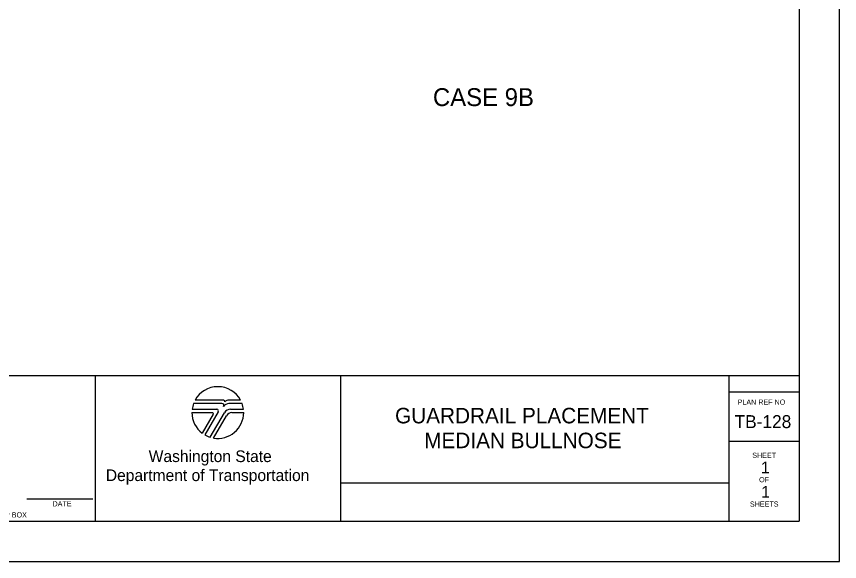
# Model space of a CAD drawing. Extents: x 1312564.5 to 1312581.5, y 1207298.4 to 1207309.4.
# Drawn here: x 1312575.12 to 1312581.48, y 1207298.42 to 1207302.64 of the extents above; entities that cross this region are included whole.
import ezdxf

# ---------------------------------------------------------------- set-up
doc = ezdxf.new("R2010")
doc.units = 0
for name, color, linetype in [('Level 1', 7, 'Continuous'), ('Level 20', 7, 'Continuous'), ('SH_GI_PlotLimits', 7, 'Continuous'), ('SH_GI_SheetBorder', 7, 'Continuous'), ('SH_GI_SheetTextInCells', 7, 'Continuous'), ('SH_GI_TitleBlockText', 7, 'Continuous'), ('SH_GI_WSDOTLogo', 7, 'Continuous')]:
    doc.layers.add(name, color=color, linetype=linetype)

msp = doc.modelspace()

# ---------------------------------------------------------------- linework, layer by layer
at = {"layer": 'SH_GI_PlotLimits'}
msp.add_lwpolyline([(1312564.478, 1207298.4209), (1312581.478, 1207298.4209), (1312581.478, 1207309.4209), (1312564.478, 1207309.4209)], close=True, dxfattribs=at)
at = {"layer": 'SH_GI_SheetBorder'}
for p, q in [((1312581.1655, 1207309.1084), (1312581.1655, 1207298.7334)), ((1312565.4155, 1207299.8593), (1312581.1655, 1207299.8593)), ((1312575.7244, 1207299.8593), (1312575.7244, 1207298.7334)), ((1312577.621, 1207299.8593), (1312577.621, 1207298.7334)), ((1312580.6233, 1207299.8593), (1312580.6233, 1207298.7334)), ((1312580.6233, 1207299.7342), (1312581.1655, 1207299.7342)), ((1312580.6233, 1207299.351), (1312581.1655, 1207299.351)), ((1312577.621, 1207299.0289), (1312580.6233, 1207299.0289)), ((1312575.1952, 1207298.9067), (1312575.7069, 1207298.9067)), ((1312565.4155, 1207298.7334), (1312581.1655, 1207298.7334))]:
    msp.add_line(p, q, dxfattribs=at)
at = {"layer": 'SH_GI_WSDOTLogo'}
for p, q in [((1312576.7185, 1207299.6688), (1312576.497, 1207299.6688)), ((1312576.8485, 1207299.6688), (1312576.7506, 1207299.6688)), ((1312576.4745, 1207299.5995), (1312576.6651, 1207299.5995)), ((1312576.7049, 1207299.6428), (1312576.4852, 1207299.6428)), ((1312576.7585, 1207299.6428), (1312576.7584, 1207299.6428)), ((1312576.8603, 1207299.6428), (1312576.7585, 1207299.6428)), ((1312576.7713, 1207299.5995), (1312576.871, 1207299.5995)), ((1312576.4727, 1207299.5734), (1312576.6303, 1207299.5734)), ((1312576.6374, 1207299.5611), (1312576.5519, 1207299.4141)), ((1312576.6765, 1207299.5798), (1312576.5722, 1207299.4006)), ((1312576.6144, 1207299.3822), (1312576.7244, 1207299.5724)), ((1312576.6399, 1207299.3762), (1312576.7397, 1207299.549)), ((1312576.7809, 1207299.5728), (1312576.8727, 1207299.5728))]:
    msp.add_line(p, q, dxfattribs=at)
for centre, radius, start, end in [((1312576.6727, 1207299.5734), 0.2, 28.47865, 151.53204), ((1312576.7184, 1207299.6597), 0.00903, 329.87418, 90.00328), ((1312576.7506, 1207299.6401), 0.0287, 90.00721, 148.16763), ((1312576.6727, 1207299.5734), 0.2, 159.69598, 172.50569), ((1312576.6651, 1207299.5864), 0.0131, 329.76834, 90), ((1312576.7049, 1207299.628), 0.0148, 327.8418, 89.99855), ((1312576.7584, 1207299.5944), 0.0484, 89.99529, 147.82376), ((1312576.7713, 1207299.5454), 0.0542, 90, 149.99738), ((1312576.6727, 1207299.5734), 0.2, 7.49431, 20.29406), ((1312576.6727, 1207299.5734), 0.2, 179.99864, 232.84327), ((1312576.6303, 1207299.5652), 0.0082, 329.74356, 90), ((1312576.6727, 1207299.5734), 0.2, 260.54554, 359.80857), ((1312576.7809, 1207299.5252), 0.0476, 90, 150.05432), ((1312576.6727, 1207299.5734), 0.2, 239.79292, 253.0448)]:
    msp.add_arc(centre, radius, start, end, dxfattribs=at)

# ---------------------------------------------------------------- texts
at = {"layer": 'Level 1'}
msp.add_text('CASE 9B', height=0.13824, dxfattribs=at).set_placement((1312578.3352, 1207301.944))
at = {"layer": 'Level 20'}
for s, p in [('GUARDRAIL PLACEMENT', (1312578.0426, 1207299.4898)), ('MEDIAN BULLNOSE', (1312578.2679, 1207299.2978))]:
    msp.add_text(s, height=0.12, dxfattribs=at).set_placement(p)
at = {"layer": 'SH_GI_SheetBorder'}
msp.add_text('PLAN REF NO', height=0.040032, dxfattribs=at).set_placement((1312580.6902, 1207299.6342))
at = {"layer": 'SH_GI_SheetTextInCells'}
for s, height, p in [('Washington State', 0.090072, (1312576.1384, 1207299.1905)), ('SHEET', 0.04003, (1312580.8032, 1207299.223)), ('Department of Transportation', 0.090072, (1312575.807, 1207299.0435)), ('OF', 0.04003, (1312580.8561, 1207299.0342)), ('DATE', 0.04003, (1312575.3949, 1207298.8475)), ('SHEETS', 0.04003, (1312580.7853, 1207298.8454)), ('P.E. STAMP BOX', 0.040032, (1312574.7545, 1207298.762))]:
    msp.add_text(s, height=height, dxfattribs=at).set_placement(p)
at = {"layer": 'SH_GI_TitleBlockText'}
for s, height, p in [('TB-128', 0.1, (1312580.6666, 1207299.4534)), ('1', 0.09, (1312580.8705, 1207299.1032)), ('1', 0.09, (1312580.873, 1207298.9152))]:
    msp.add_text(s, height=height, dxfattribs=at).set_placement(p)

doc.saveas('drawing.dxf')
